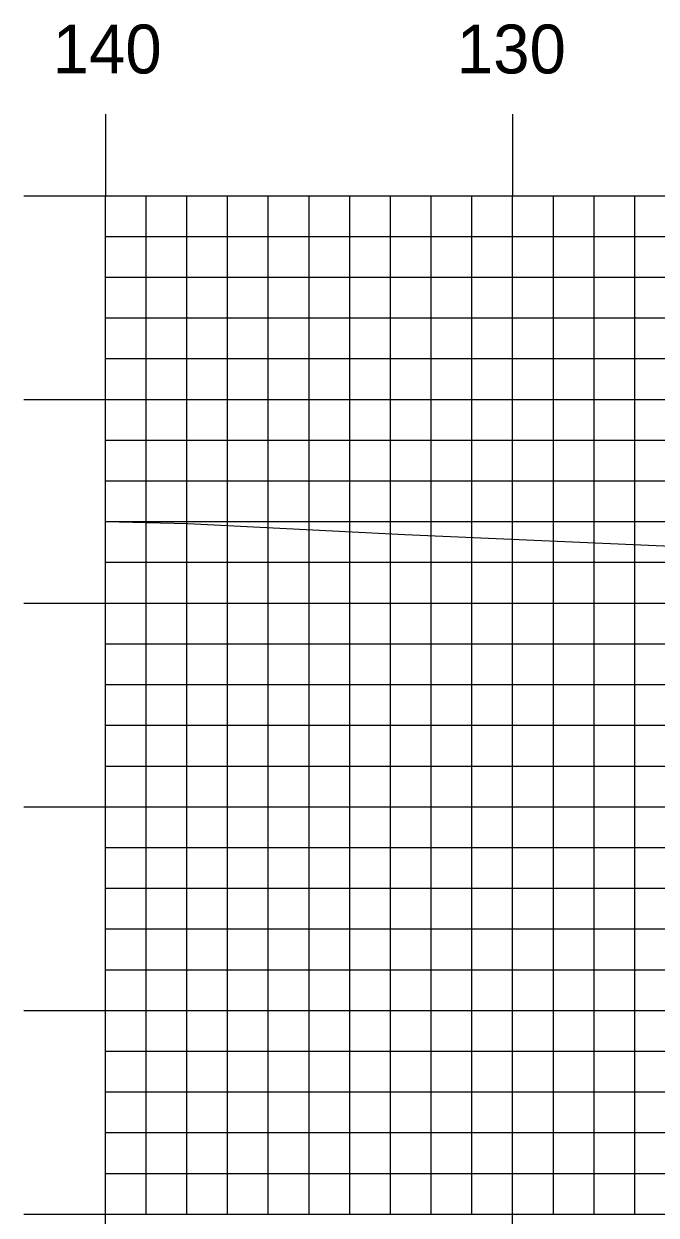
# Model space of a CAD drawing. Extents: x 1771235 to 1771579, y 442591 to 442811.
# Drawn here: x 1771259.06 to 1771274.59, y 442608.64 to 442637.88 of the extents above; entities that cross this region are included whole.
import ezdxf

# ---------------------------------------------------------------- set-up
doc = ezdxf.new("R2010")
doc.units = 0
for name, color, linetype in [('H_V ANNOTATION', 7, 'Continuous'), ('MAJOR', 7, 'Continuous'), ('MINOR', 7, 'Continuous'), ('S_Roadway_Centerline', 7, 'Continuous')]:
    doc.layers.add(name, color=color, linetype=linetype)

msp = doc.modelspace()

# ---------------------------------------------------------------- linework, layer by layer
at = {"layer": 'MAJOR'}
for p, q in [((1771261.067, 442635.669), (1771261.067, 442633.665)), ((1771271.067, 442635.669), (1771271.067, 442633.665)), ((1771259.063, 442633.665), (1771261.067, 442633.665)), ((1771261.067, 442633.665), (1771541.067, 442633.665)), ((1771261.067, 442608.665), (1771261.067, 442633.665)), ((1771261.067, 442608.665), (1771261.067, 442633.665)), ((1771261.067, 442633.665), (1771541.067, 442633.665)), ((1771271.067, 442608.665), (1771271.067, 442633.665)), ((1771259.063, 442628.665), (1771261.067, 442628.665)), ((1771261.067, 442628.665), (1771541.067, 442628.665)), ((1771259.063, 442623.665), (1771261.067, 442623.665)), ((1771261.067, 442623.665), (1771541.067, 442623.665)), ((1771259.063, 442618.665), (1771261.067, 442618.665)), ((1771261.067, 442618.665), (1771541.067, 442618.665)), ((1771259.063, 442613.665), (1771261.067, 442613.665)), ((1771261.067, 442613.665), (1771541.067, 442613.665)), ((1771259.063, 442608.665), (1771261.067, 442608.665)), ((1771261.067, 442608.665), (1771541.067, 442608.665)), ((1771261.067, 442608.665), (1771541.067, 442608.665)), ((1771261.067, 442606.661), (1771261.067, 442608.665)), ((1771271.067, 442606.661), (1771271.067, 442608.665))]:
    msp.add_line(p, q, dxfattribs=at)
at = {"layer": 'MINOR'}
for p, q in [((1771262.067, 442608.665), (1771262.067, 442633.665)), ((1771263.067, 442608.665), (1771263.067, 442633.665)), ((1771264.067, 442608.665), (1771264.067, 442633.665)), ((1771265.067, 442608.665), (1771265.067, 442633.665)), ((1771266.067, 442608.665), (1771266.067, 442633.665)), ((1771267.067, 442608.665), (1771267.067, 442633.665)), ((1771268.067, 442608.665), (1771268.067, 442633.665)), ((1771269.067, 442608.665), (1771269.067, 442633.665)), ((1771270.067, 442608.665), (1771270.067, 442633.665)), ((1771272.067, 442608.665), (1771272.067, 442633.665)), ((1771273.067, 442608.665), (1771273.067, 442633.665)), ((1771274.067, 442608.665), (1771274.067, 442633.665)), ((1771261.067, 442632.665), (1771541.067, 442632.665)), ((1771261.067, 442632.665), (1771263.071, 442632.665)), ((1771261.067, 442631.665), (1771541.067, 442631.665)), ((1771261.067, 442631.665), (1771263.071, 442631.665)), ((1771261.067, 442630.665), (1771541.067, 442630.665)), ((1771261.067, 442630.665), (1771263.071, 442630.665)), ((1771261.067, 442629.665), (1771541.067, 442629.665)), ((1771261.067, 442629.665), (1771263.071, 442629.665)), ((1771261.067, 442627.665), (1771541.067, 442627.665)), ((1771261.067, 442627.665), (1771263.071, 442627.665)), ((1771261.067, 442626.665), (1771541.067, 442626.665)), ((1771261.067, 442626.665), (1771263.071, 442626.665)), ((1771261.067, 442625.665), (1771541.067, 442625.665)), ((1771261.067, 442625.665), (1771263.071, 442625.665)), ((1771261.067, 442624.665), (1771541.067, 442624.665)), ((1771261.067, 442624.665), (1771263.071, 442624.665)), ((1771261.067, 442622.665), (1771541.067, 442622.665)), ((1771261.067, 442622.665), (1771263.071, 442622.665)), ((1771261.067, 442621.665), (1771541.067, 442621.665)), ((1771261.067, 442621.665), (1771263.071, 442621.665)), ((1771261.067, 442620.665), (1771541.067, 442620.665)), ((1771261.067, 442620.665), (1771263.071, 442620.665)), ((1771261.067, 442619.665), (1771541.067, 442619.665)), ((1771261.067, 442619.665), (1771263.071, 442619.665)), ((1771261.067, 442617.665), (1771541.067, 442617.665)), ((1771261.067, 442617.665), (1771263.071, 442617.665)), ((1771261.067, 442616.665), (1771541.067, 442616.665)), ((1771261.067, 442616.665), (1771263.071, 442616.665)), ((1771261.067, 442615.665), (1771541.067, 442615.665)), ((1771261.067, 442615.665), (1771263.071, 442615.665)), ((1771261.067, 442614.665), (1771541.067, 442614.665)), ((1771261.067, 442614.665), (1771263.071, 442614.665)), ((1771261.067, 442612.665), (1771541.067, 442612.665)), ((1771261.067, 442612.665), (1771263.071, 442612.665)), ((1771261.067, 442611.665), (1771541.067, 442611.665)), ((1771261.067, 442611.665), (1771263.071, 442611.665)), ((1771261.067, 442610.665), (1771541.067, 442610.665)), ((1771261.067, 442610.665), (1771263.071, 442610.665)), ((1771261.067, 442609.665), (1771541.067, 442609.665)), ((1771261.067, 442609.665), (1771263.071, 442609.665))]:
    msp.add_line(p, q, dxfattribs=at)
at = {"layer": 'S_Roadway_Centerline'}
msp.add_lwpolyline([(1771261.067, 442625.671), (1771263.095, 442625.617), (1771268.422, 442625.35), (1771275.522, 442625.038), (1771285.624, 442624.666), (1771286.784, 442624.651), (1771287.698, 442624.665), (1771298.589, 442624.703), (1771309.404, 442624.118), (1771311.113, 442624.118), (1771313.33, 442624.077), (1771328.929, 442623.769), (1771334.708, 442623.416), (1771344.096, 442623.092), (1771347.049, 442623.018)], dxfattribs=at)

# ---------------------------------------------------------------- texts
at = {"layer": 'H_V ANNOTATION'}
for s, p in [('140', (1771259.772, 442636.665)), ('130', (1771269.697, 442636.665))]:
    msp.add_text(s, height=1.2, dxfattribs=at).set_placement(p)
at = {"layer": 'MAJOR'}
msp.add_text('-', height=0.012, dxfattribs=at).set_placement((1771261.058, 442608.665))

doc.saveas('drawing.dxf')
